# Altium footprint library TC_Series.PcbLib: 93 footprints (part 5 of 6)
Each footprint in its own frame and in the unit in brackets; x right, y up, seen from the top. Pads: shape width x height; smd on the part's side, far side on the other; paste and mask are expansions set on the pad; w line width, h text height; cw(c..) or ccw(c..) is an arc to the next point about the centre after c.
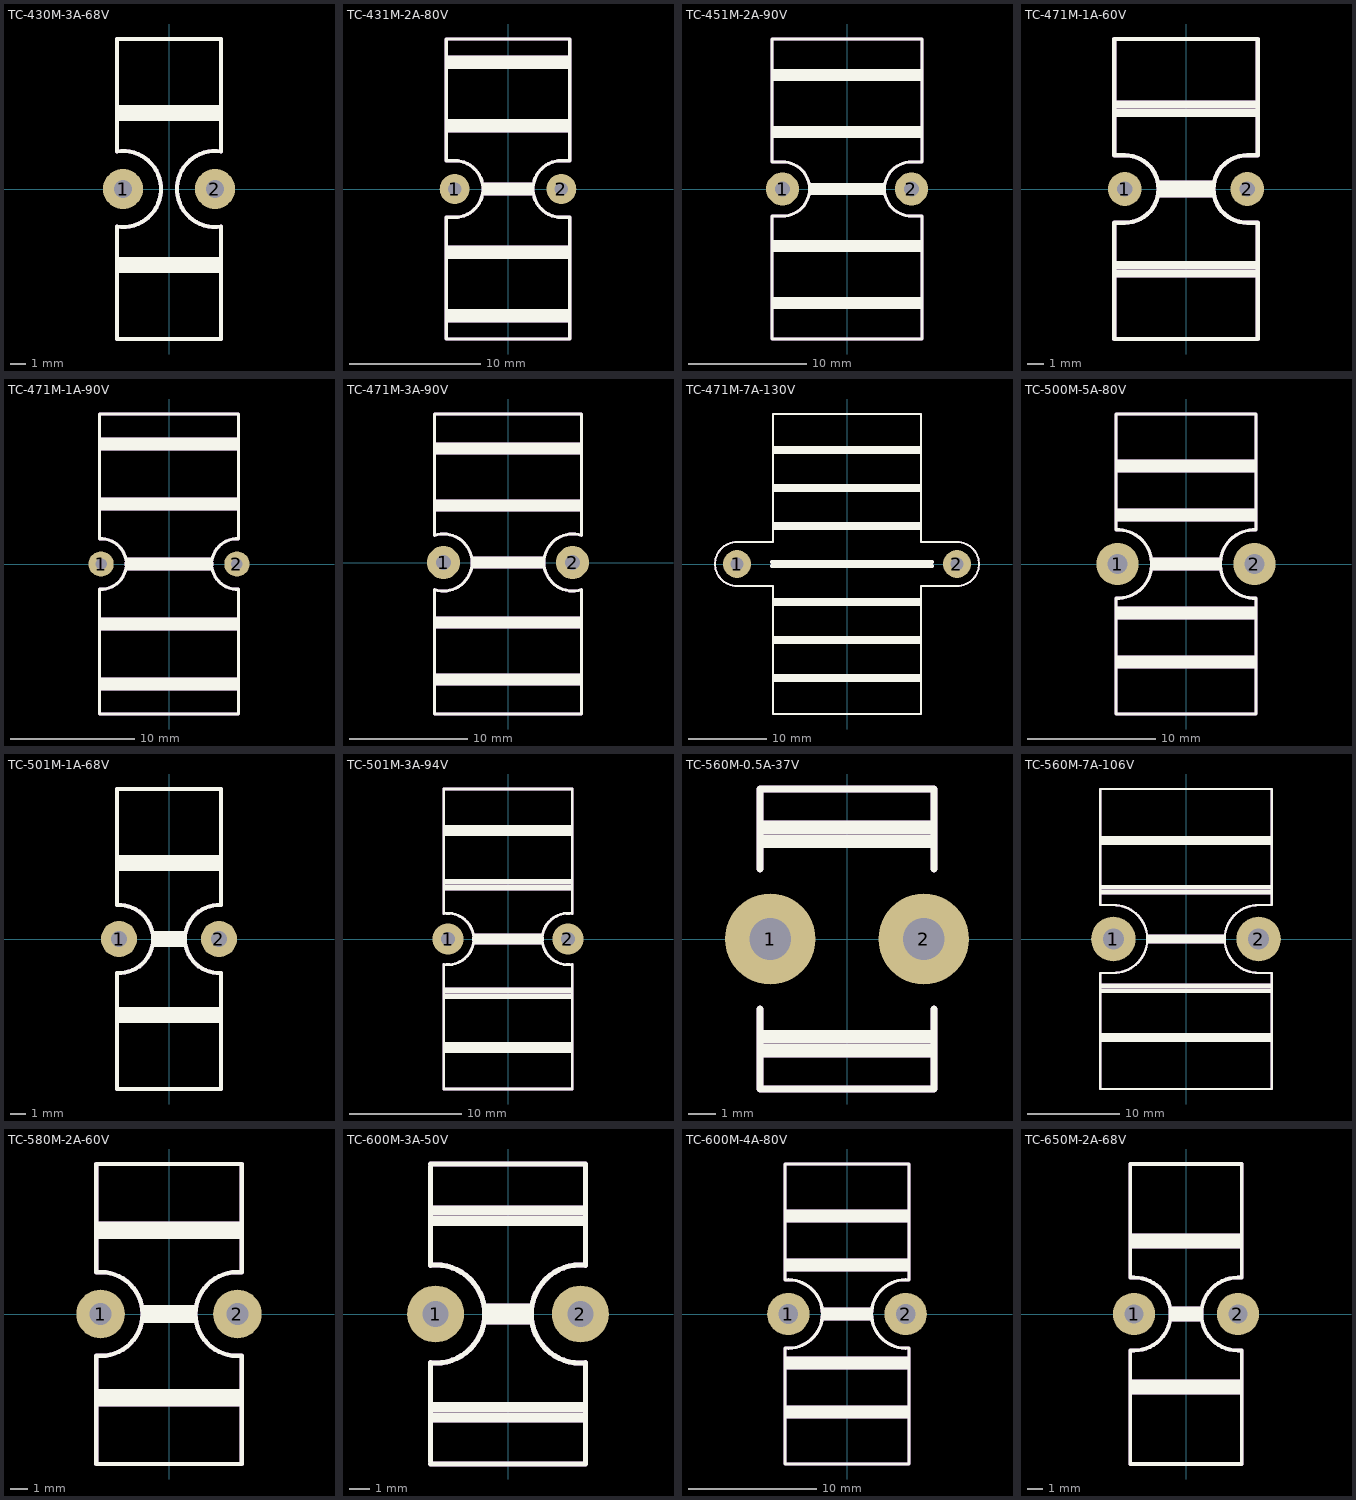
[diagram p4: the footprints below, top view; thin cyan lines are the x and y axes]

## TC-430M-3A-68V [mil]
pads (2):
  round 100 hole 46: 1(-115,0) 2(115,0)
Top Overlay:
  lines w10: -130,-93.84 -130,-375 130,-375 130,-93.84 ; -130,93.84 -130,375 130,375 130,93.84 ; -129.82,-93.84 ccw(c-115,0) -129.82,93.84 ; 129.82,-93.84 cw(c115,0) 129.82,93.84
  lines w19.68: -125,-200 125,-200 ; -125,-180 125,-180 ; -125,180 125,180 ; -125,200 125,200
Mechanical 29:
  lines w10: -130,-93.84 -130,-375 130,-375 130,-93.84 ; -130,93.84 -130,375 130,375 130,93.84 ; -129.82,-93.84 ccw(c-115,0) -129.82,93.84 ; 129.82,-93.84 cw(c115,0) 129.82,93.84
  lines w19.68: -125,-200 125,-200 ; -125,-180 125,-180 ; -125,180 125,180 ; -125,200 125,200
  text "'.Designator'" at -1750,-64.85 h400

## TC-431M-2A-80V [mil]
pads (2):
  round 90 hole 40: 1(-160,0) 2(160,0)
Top Overlay:
  lines w10: -185,-450 185,-450 185,-85 160,-85 cw(c160,0) 160,85 185,85 185,450 -185,450 -185,85 -160,85 cw(c-160,0) -160,-85 -185,-85 -185,-450
  lines w19.68: -180,-390 180,-390 ; -180,-370 180,-370 ; -180,-200 180,-200 ; -180,-180 180,-180 ; -180,180 180,180 ; -180,200 180,200 ; -180,370 180,370 ; -180,390 180,390 ; -70,-10 70,-10 ; -70,10 70,10
Mechanical 29:
  lines w10: -185,-450 185,-450 185,-85 160,-85 cw(c160,0) 160,85 185,85 185,450 -185,450 -185,85 -160,85 cw(c-160,0) -160,-85 -185,-85 -185,-450
  lines w19.68: -180,-390 180,-390 ; -180,-370 180,-370 ; -180,-200 180,-200 ; -180,-180 180,-180 ; -180,180 180,180 ; -180,200 180,200 ; -180,370 180,370 ; -180,390 180,390 ; -70,-10 70,-10 ; -70,10 70,10
  text "'.Designator'" at -1750,-64.85 h400

## TC-451M-2A-90V [mil]
pads (2):
  round 110 hole 50: 1(-215,0) 2(215,0)
Top Overlay:
  lines w10: -250,-500 250,-500 250,-90 215,-90 cw(c215,0) 215,90 250,90 250,500 -250,500 -250,90 -215,90 cw(c-215,0) -215,-90 -250,-90 -250,-500
  lines w19.68: -245,-390 245,-390 ; -245,-370 245,-370 ; -245,-200 245,-200 ; -245,-180 245,-180 ; -245,180 245,180 ; -245,200 245,200 ; -245,370 245,370 ; -245,390 245,390 ; -120,-10 120,-10 ; -120,10 120,10
Mechanical 29:
  lines w10: -250,-500 250,-500 250,-90 215,-90 cw(c215,0) 215,90 250,90 250,500 -250,500 -250,90 -215,90 cw(c-215,0) -215,-90 -250,-90 -250,-500
  lines w19.68: -245,-390 245,-390 ; -245,-370 245,-370 ; -245,-200 245,-200 ; -245,-180 245,-180 ; -245,180 245,180 ; -245,200 245,200 ; -245,370 245,370 ; -245,390 245,390 ; -120,-10 120,-10 ; -120,10 120,10
  text "'.Designator'" at -1750,-64.85 h400

## TC-471M-1A-60V [mil]
pads (2):
  round 80 hole 36: 1(-145,0) 2(145,0)
Top Overlay:
  lines w10: -170,-355 170,-355 170,-80 145,-80 cw(c145,0) 145,80 170,80 170,355 -170,355 -170,80 -145,80 cw(c-145,0) -145,-80 -170,-80 -170,-355
  lines w19.68: -165,-200 165,-200 ; -165,-180 165,-180 ; -165,180 165,180 ; -165,200 165,200 ; -60,-10 60,-10 ; -60,10 60,10
Mechanical 29:
  lines w10: -170,-355 170,-355 170,-80 145,-80 cw(c145,0) 145,80 170,80 170,355 -170,355 -170,80 -145,80 cw(c-145,0) -145,-80 -170,-80 -170,-355
  lines w19.68: -165,-200 165,-200 ; -165,-180 165,-180 ; -165,180 165,180 ; -165,200 165,200 ; -60,-10 60,-10 ; -60,10 60,10
  text "'.Designator'" at -1750,-64.85 h400

## TC-471M-1A-90V [mil]
pads (2):
  round 80 hole 36: 1(-215,0) 2(215,0)
Top Overlay:
  lines w10: -220,-79.86 -220,-475 220,-475 220,-80 ; -219.99,79.84 cw(c-215,0) -219.7,-79.86 ; -220,80 -220,475 220,475 220,80 ; 219.99,-79.84 cw(c215,0) 219.99,79.84
  lines w19.68: -215,-390 215,-390 ; -215,-370 215,-370 ; -215,-200 215,-200 ; -215,-180 215,-180 ; -215,180 215,180 ; -215,200 215,200 ; -215,370 215,370 ; -215,390 215,390 ; -130,-10 130,-10 ; -130,10 130,10
Mechanical 29:
  lines w10: -220,-79.86 -220,-475 220,-475 220,-80 ; -219.99,79.84 cw(c-215,0) -219.7,-79.86 ; -220,80 -220,475 220,475 220,80 ; 219.99,-79.84 cw(c215,0) 219.99,79.84
  lines w19.68: -215,-390 215,-390 ; -215,-370 215,-370 ; -215,-200 215,-200 ; -215,-180 215,-180 ; -215,180 215,180 ; -215,200 215,200 ; -215,370 215,370 ; -215,390 215,390 ; -130,-10 130,-10 ; -130,10 130,10
  text "'.Designator'" at -1750,-64.85 h400

## TC-471M-3A-90V [mil]
pads (2):
  round 110 hole 50: 1(-215,0) 2(215,0)
Top Overlay:
  lines w10: -245,-90.25 -245,-505 245,-505 245,-90.26 ; -245,90.2 -245,495 245,495 245,90.2 ; -244.8,90.2 cw(c-215,0) -244.67,-90.25 ; 244.64,-90.26 cw(c215,0) 244.8,90.2
  lines w19.68: -240,-400 240,-400 ; -240,-380 240,-380 ; -240,-210 240,-210 ; -240,-190 240,-190 ; -240,180 240,180 ; -240,200 240,200 ; -240,370 240,370 ; -240,390 240,390 ; -115,-10 115,-10 ; -115,10 115,10
Mechanical 29:
  lines w10: -245,-90.25 -245,-505 245,-505 245,-90.26 ; -245,90.2 -245,495 245,495 245,90.2 ; -244.8,90.2 cw(c-215,0) -244.67,-90.25 ; 244.64,-90.26 cw(c215,0) 244.8,90.2
  lines w19.68: -240,-400 240,-400 ; -240,-380 240,-380 ; -240,-210 240,-210 ; -240,-190 240,-190 ; -240,180 240,180 ; -240,200 240,200 ; -240,370 240,370 ; -240,390 240,390 ; -115,-10 115,-10 ; -115,10 115,10
  text "'.Designator'" at -1750,-64.85 h400

## TC-471M-7A-130V [mil]
pads (2):
  round 140 hole 67: 1(-550,0) 2(550,0)
Top Overlay:
  lines w10: -550,-110 cw(c-550,0) -550,110 -370,110 -370,750 370,750 370,110 550,110 cw(c550,0) 550,-110 370,-110 370,-750 -370,-750 -370,-110 -550,-110
  lines w19.68: -375,-10 425,-10 ; -375,10 425,10 ; -365,-580 365,-580 ; -365,-560 365,-560 ; -365,-390 365,-390 ; -365,-370 365,-370 ; -365,-200 365,-200 ; -365,-180 365,-180 ; -365,180 365,180 ; -365,200 365,200 ; -365,370 365,370 ; -365,390 365,390 ; -365,560 365,560 ; -365,580 365,580
Mechanical 29:
  lines w10: -550,-110 cw(c-550,0) -550,110 -370,110 -370,750 370,750 370,110 550,110 cw(c550,0) 550,-110 370,-110 370,-750 -370,-750 -370,-110 -550,-110
  lines w19.68: -375,-10 425,-10 ; -375,10 425,10 ; -365,-580 365,-580 ; -365,-560 365,-560 ; -365,-390 365,-390 ; -365,-370 365,-370 ; -365,-200 365,-200 ; -365,-180 365,-180 ; -365,180 365,180 ; -365,200 365,200 ; -365,370 365,370 ; -365,390 365,390 ; -365,560 365,560 ; -365,580 365,580
  text "'.Designator'" at -1750,-64.85 h400

## TC-500M-5A-80V [mil]
pads (2):
  round 130 hole 60: 1(-210,0) 2(210,0)
Top Overlay:
  lines w10: -215,-104.88 ccw(c-210,0) -215,104.88 ; -215,-104.82 -215,-460 215,-460 ; -215,104.82 -215,460 215,460 ; 215,-459.83 215,-104.82 ; 215,-104.88 cw(c210,0) 215,104.88 ; 215,104.82 215,459.83
  lines w19.68: -210,-310 210,-310 ; -210,-290 210,-290 ; -210,-160 210,-160 ; -210,-140 210,-140 ; -210,140 210,140 ; -210,160 210,160 ; -210,290 210,290 ; -210,310 210,310 ; -100,-10 100,-10 ; -100,10 100,10
Mechanical 29:
  lines w10: -215,-104.88 ccw(c-210,0) -215,104.88 ; -215,-104.82 -215,-460 215,-460 ; -215,104.82 -215,460 215,460 ; 215,-459.83 215,-104.82 ; 215,-104.88 cw(c210,0) 215,104.88 ; 215,104.82 215,459.83
  lines w19.68: -210,-310 210,-310 ; -210,-290 210,-290 ; -210,-160 210,-160 ; -210,-140 210,-140 ; -210,140 210,140 ; -210,160 210,160 ; -210,290 210,290 ; -210,310 210,310 ; -100,-10 100,-10 ; -100,10 100,10
  text "'.Designator'" at -1750,-64.85 h400

## TC-501M-1A-68V [mil]
pads (2):
  round 90 hole 40: 1(-125,0) 2(125,0)
Top Overlay:
  lines w10: -130,-85 -130,-375 130,-375 130,-85 ; -129.99,-84.85 ccw(c-125,0) -129.99,84.85 ; -130,85 -130,375 130,375 130,84.83 ccw(c125,0) 129.99,-84.85
  lines w19.68: -125,-200 125,-200 ; -125,-180 125,-180 ; -125,180 125,180 ; -125,200 125,200 ; -35,-10 35,-10 ; -35,10 35,10
Mechanical 29:
  lines w10: -130,-85 -130,-375 130,-375 130,-85 ; -129.99,-84.85 ccw(c-125,0) -129.99,84.85 ; -130,85 -130,375 130,375 130,84.83 ccw(c125,0) 129.99,-84.85
  lines w19.68: -125,-200 125,-200 ; -125,-180 125,-180 ; -125,180 125,180 ; -125,200 125,200 ; -35,-10 35,-10 ; -35,10 35,10
  text "'.Designator'" at -1750,-64.85 h400

## TC-501M-3A-94V [mil]
pads (2):
  round 110 hole 50: 1(-210,0) 2(210,0)
Top Overlay:
  lines w10: 225,-88.74 cw(c210,0) 225,88.74 ; 225,-88.63 225,-525 -225,-525 -225,-88.74 ccw(c-210,0) -225,88.74 -225,525 225,525 225,88.63
  lines w19.68: -220,-390 220,-390 ; -220,-370 220,-370 ; -220,-200 220,-200 ; -220,-180 220,-180 ; -220,180 220,180 ; -220,200 220,200 ; -220,370 220,370 ; -220,390 220,390 ; -115,-10 115,-10 ; -115,10 115,10
Mechanical 29:
  lines w10: 225,-88.74 cw(c210,0) 225,88.74 ; 225,-88.63 225,-525 -225,-525 -225,-88.74 ccw(c-210,0) -225,88.74 -225,525 225,525 225,88.63
  lines w19.68: -220,-390 220,-390 ; -220,-370 220,-370 ; -220,-200 220,-200 ; -220,-180 220,-180 ; -220,180 220,180 ; -220,200 220,200 ; -220,370 220,370 ; -220,390 220,390 ; -115,-10 115,-10 ; -115,10 115,10
  text "'.Designator'" at -1750,-64.85 h400

## TC-560M-0.5A-37V [mil]
pads (2):
  round 130 hole 60: 1(-110,0) 2(110,0)
Top Overlay:
  lines w10: -125,-100 -125,-215 125,-215 125,-100 ; -125,100 -125,215 125,215 125,100
  lines w19.68: -120,-160 120,-160 ; -120,-140 120,-140 ; -120,140 120,140 ; -120,160 120,160
Mechanical 29:
  lines w10: -125,-100 -125,-215 125,-215 125,-100 ; -125,100 -125,215 125,215 125,100
  lines w19.68: -120,-160 120,-160 ; -120,-140 120,-140 ; -120,140 120,140 ; -120,160 120,160
  text "'.Designator'" at -1750,-64.85 h400

## TC-560M-7A-106V [mil]
pads (2):
  round 190 hole 90: 1(-310,0) 2(310,0)
Top Overlay:
  lines w10: -365.5,-145.5 -365.5,-640 365.5,-640 365.5,-145 310,-145 cw(c310,0) 310,145 365.5,145 365.5,640 -365.5,640 -365.5,145.5 -365,145 -310,145 cw(c-310,0) -310,-145 -365,-145
  lines w19.68: -360,-430 360,-430 ; -360,-410 360,-410 ; -360,-220 360,-220 ; -360,-200 360,-200 ; -360,200 360,200 ; -360,220 360,220 ; -360,410 360,410 ; -360,430 360,430 ; -160,-10 160,-10 ; -160,10 160,10
Mechanical 29:
  lines w10: -365.5,-145.5 -365.5,-640 365.5,-640 365.5,-145 310,-145 cw(c310,0) 310,145 365.5,145 365.5,640 -365.5,640 -365.5,145.5 -365,145 -310,145 cw(c-310,0) -310,-145 -365,-145
  lines w19.68: -360,-430 360,-430 ; -360,-410 360,-410 ; -360,-220 360,-220 ; -360,-200 360,-200 ; -360,200 360,200 ; -360,220 360,220 ; -360,410 360,410 ; -360,430 360,430 ; -160,-10 160,-10 ; -160,10 160,10
  text "'.Designator'" at -1750,-64.85 h400

## TC-580M-2A-60V [mil]
pads (2):
  round 110 hole 50: 1(-155,0) 2(155,0)
Top Overlay:
  lines w10: -165,-95 -165,-340 165,-340 165,-95 ; -165,95 -165,340 165,340 165,95 ; -164.95,-94.48 ccw(c-155,0) -164.95,94.48 ; 164.95,-94.48 cw(c155,0) 164.95,94.48
  lines w19.68: -160,-200 160,-200 ; -160,-180 160,-180 ; -160,180 160,180 ; -160,200 160,200 ; -55,-10 55,-10 ; -55,10 55,10
Mechanical 29:
  lines w10: -165,-95 -165,-340 165,-340 165,-95 ; -165,95 -165,340 165,340 165,95 ; -164.95,-94.48 ccw(c-155,0) -164.95,94.48 ; 164.95,-94.48 cw(c155,0) 164.95,94.48
  lines w19.68: -160,-200 160,-200 ; -160,-180 160,-180 ; -160,180 160,180 ; -160,200 160,200 ; -55,-10 55,-10 ; -55,10 55,10
  text "'.Designator'" at -1750,-64.85 h400

## TC-600M-3A-50V [mil]
pads (2):
  round 110 hole 50: 1(-140,0) 2(140,0)
Top Overlay:
  lines w10: -150,-290 150,-290 150,-94.35 ; -150,-285 -150,-94.35 ; -150,-94.47 ccw(c-140,0) -150,94.47 ; -150,94.35 -150,285 ; -150,290 150,290 150,94.35 ; 150,-94.47 cw(c140,0) 150,94.47
  lines w19.68: -145,-200 145,-200 ; -145,-180 145,-180 ; -145,180 145,180 ; -145,200 145,200 ; -40,-10 40,-10 ; -40,10 40,10
Mechanical 29:
  lines w10: -150,-290 150,-290 150,-94.35 ; -150,-285 -150,-94.35 ; -150,-94.47 ccw(c-140,0) -150,94.47 ; -150,94.35 -150,285 ; -150,290 150,290 150,94.35 ; 150,-94.47 cw(c140,0) 150,94.47
  lines w19.68: -145,-200 145,-200 ; -145,-180 145,-180 ; -145,180 145,180 ; -145,200 145,200 ; -40,-10 40,-10 ; -40,10 40,10
  text "'.Designator'" at -1750,-64.85 h400

## TC-600M-4A-80V [mil]
pads (2):
  round 130 hole 60: 1(-180,0) 2(180,0)
Top Overlay:
  lines w10: -190,-104.53 -190,-460 190,-460 190,-105 ; -190,-104.52 ccw(c-180,0) -189.95,104.53 ; -190,104.53 -190,460 190,460 190,105 ; 189.96,-104.53 cw(c180,0) 189.95,104.53
  lines w19.68: -185,-310 185,-310 ; -185,-290 185,-290 ; -185,-160 185,-160 ; -185,-140 185,-140 ; -185,140 185,140 ; -185,160 185,160 ; -185,290 185,290 ; -185,310 185,310 ; -70,-10 70,-10 ; -70,10 70,10
Mechanical 29:
  lines w10: -190,-104.53 -190,-460 190,-460 190,-105 ; -190,-104.52 ccw(c-180,0) -189.95,104.53 ; -190,104.53 -190,460 190,460 190,105 ; 189.96,-104.53 cw(c180,0) 189.95,104.53
  lines w19.68: -185,-310 185,-310 ; -185,-290 185,-290 ; -185,-160 185,-160 ; -185,-140 185,-140 ; -185,140 185,140 ; -185,160 185,160 ; -185,290 185,290 ; -185,310 185,310 ; -70,-10 70,-10 ; -70,10 70,10
  text "'.Designator'" at -1750,-64.85 h400

## TC-650M-2A-68V [mil]
pads (2):
  round 110 hole 50: 1(-135,0) 2(135,0)
Top Overlay:
  lines w10: -145.07,94.47 cw(c-135,0) -145,-94.47 -145,-390 145,-390 145,-94.47 cw(c135,0) 145,94.47 ; -145,94.47 -145,390 145,390 145,94.35
  lines w19.68: -140,-200 140,-200 ; -140,-180 140,-180 ; -140,180 140,180 ; -140,200 140,200 ; -35,-10 35,-10 ; -35,10 35,10
Mechanical 29:
  lines w10: -145.07,94.47 cw(c-135,0) -145,-94.47 -145,-390 145,-390 145,-94.47 cw(c135,0) 145,94.47 ; -145,94.47 -145,390 145,390 145,94.35
  lines w19.68: -140,-200 140,-200 ; -140,-180 140,-180 ; -140,180 140,180 ; -140,200 140,200 ; -35,-10 35,-10 ; -35,10 35,10
  text "'.Designator'" at -1750,-64.85 h400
